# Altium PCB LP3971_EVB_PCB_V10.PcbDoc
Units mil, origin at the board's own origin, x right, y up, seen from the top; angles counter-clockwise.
Board outline 4000 x 4200 mil, 4 copper layers (Top Layer, InternalPlane1, InternalPlane2, Bottom Layer), stack 62 mil thick; 86 components, 62 nets, 253 pads, 86 vias.
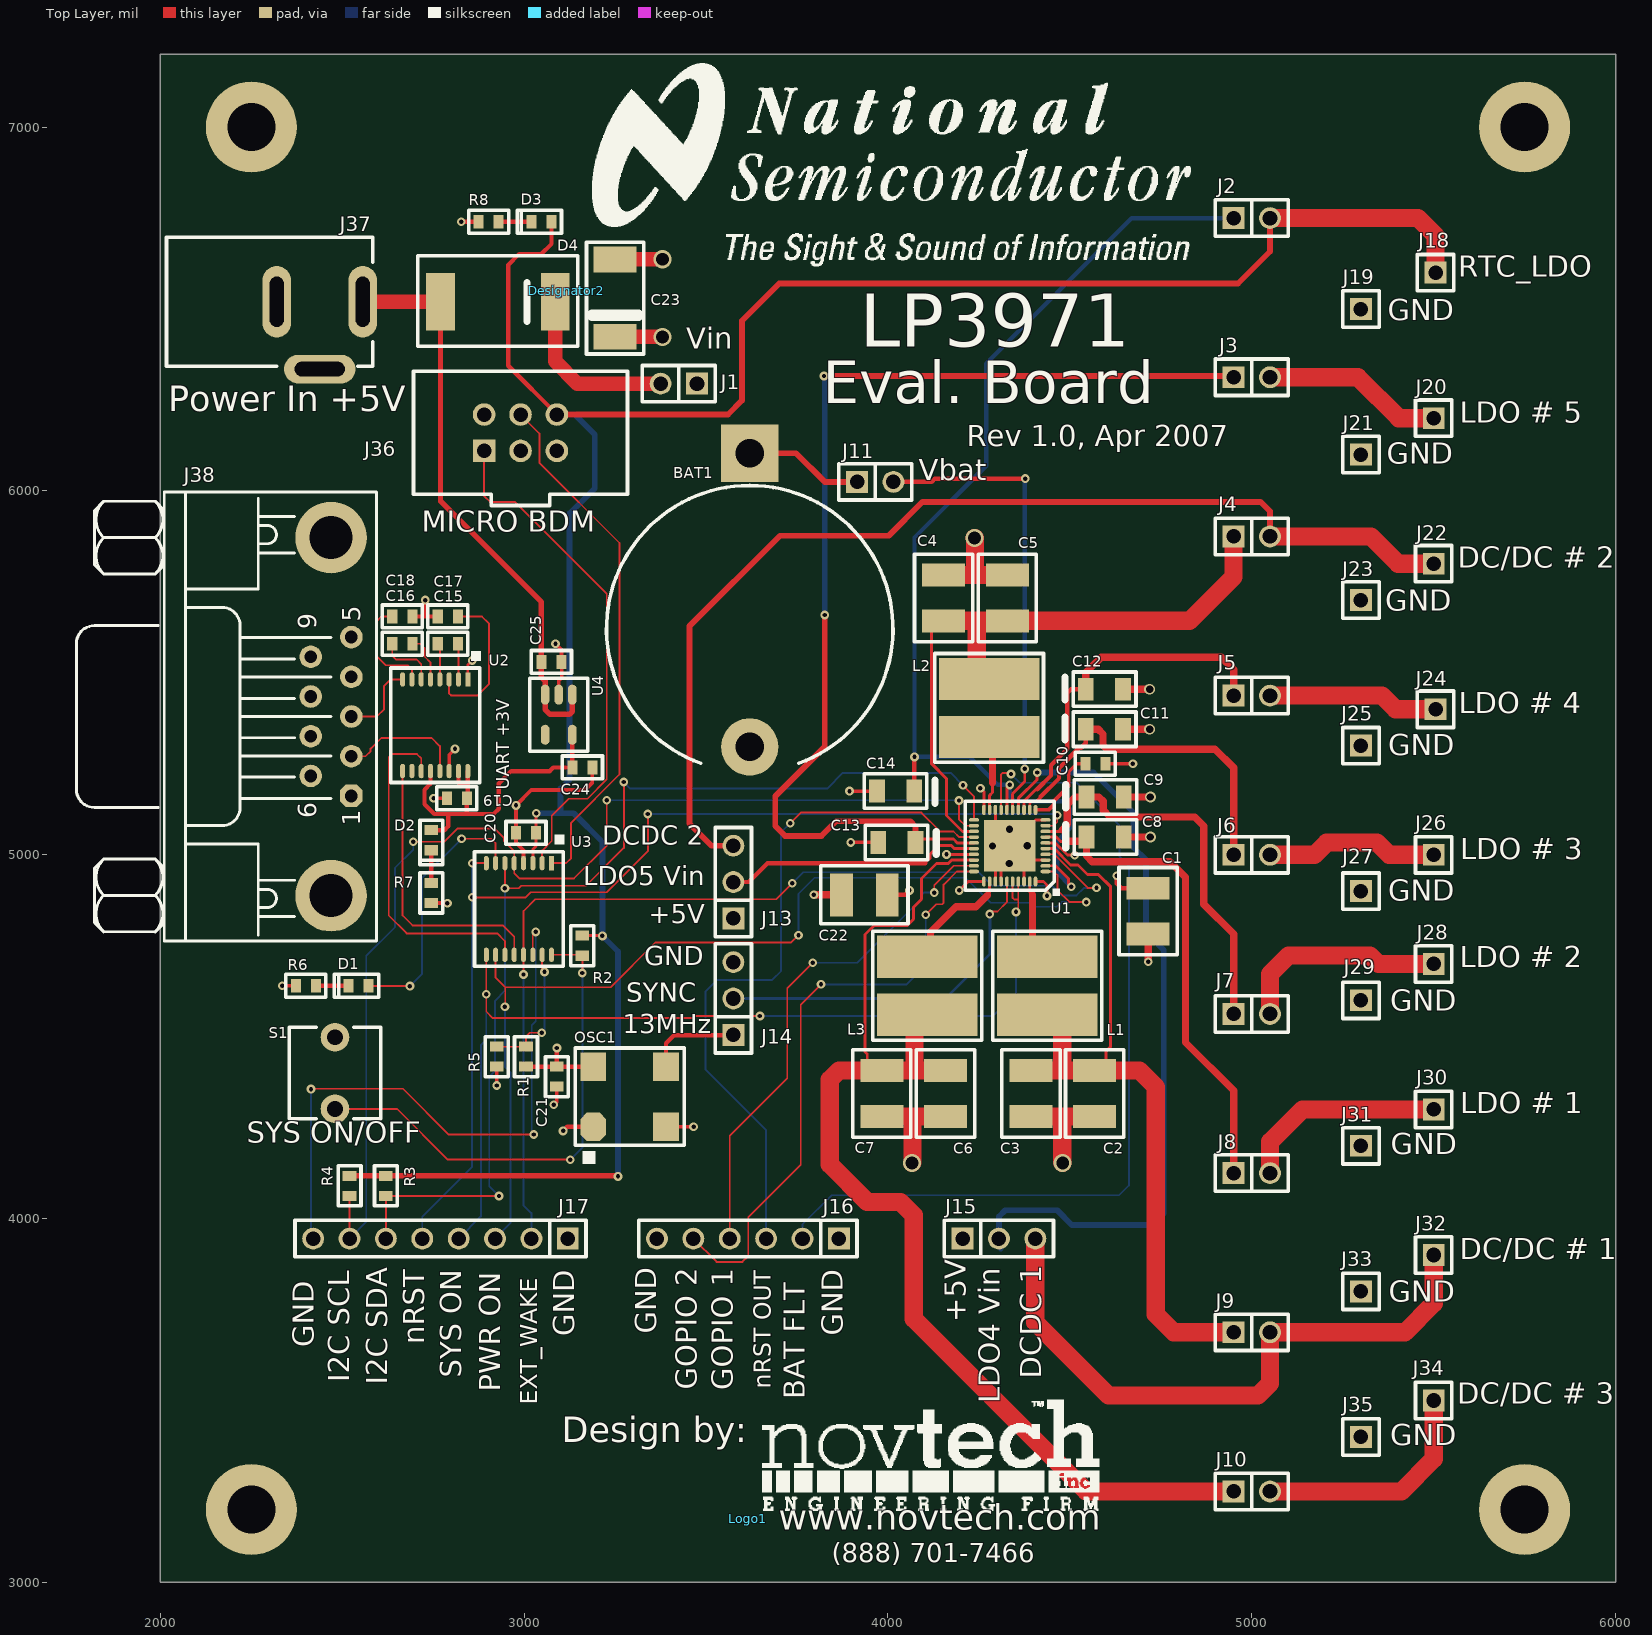
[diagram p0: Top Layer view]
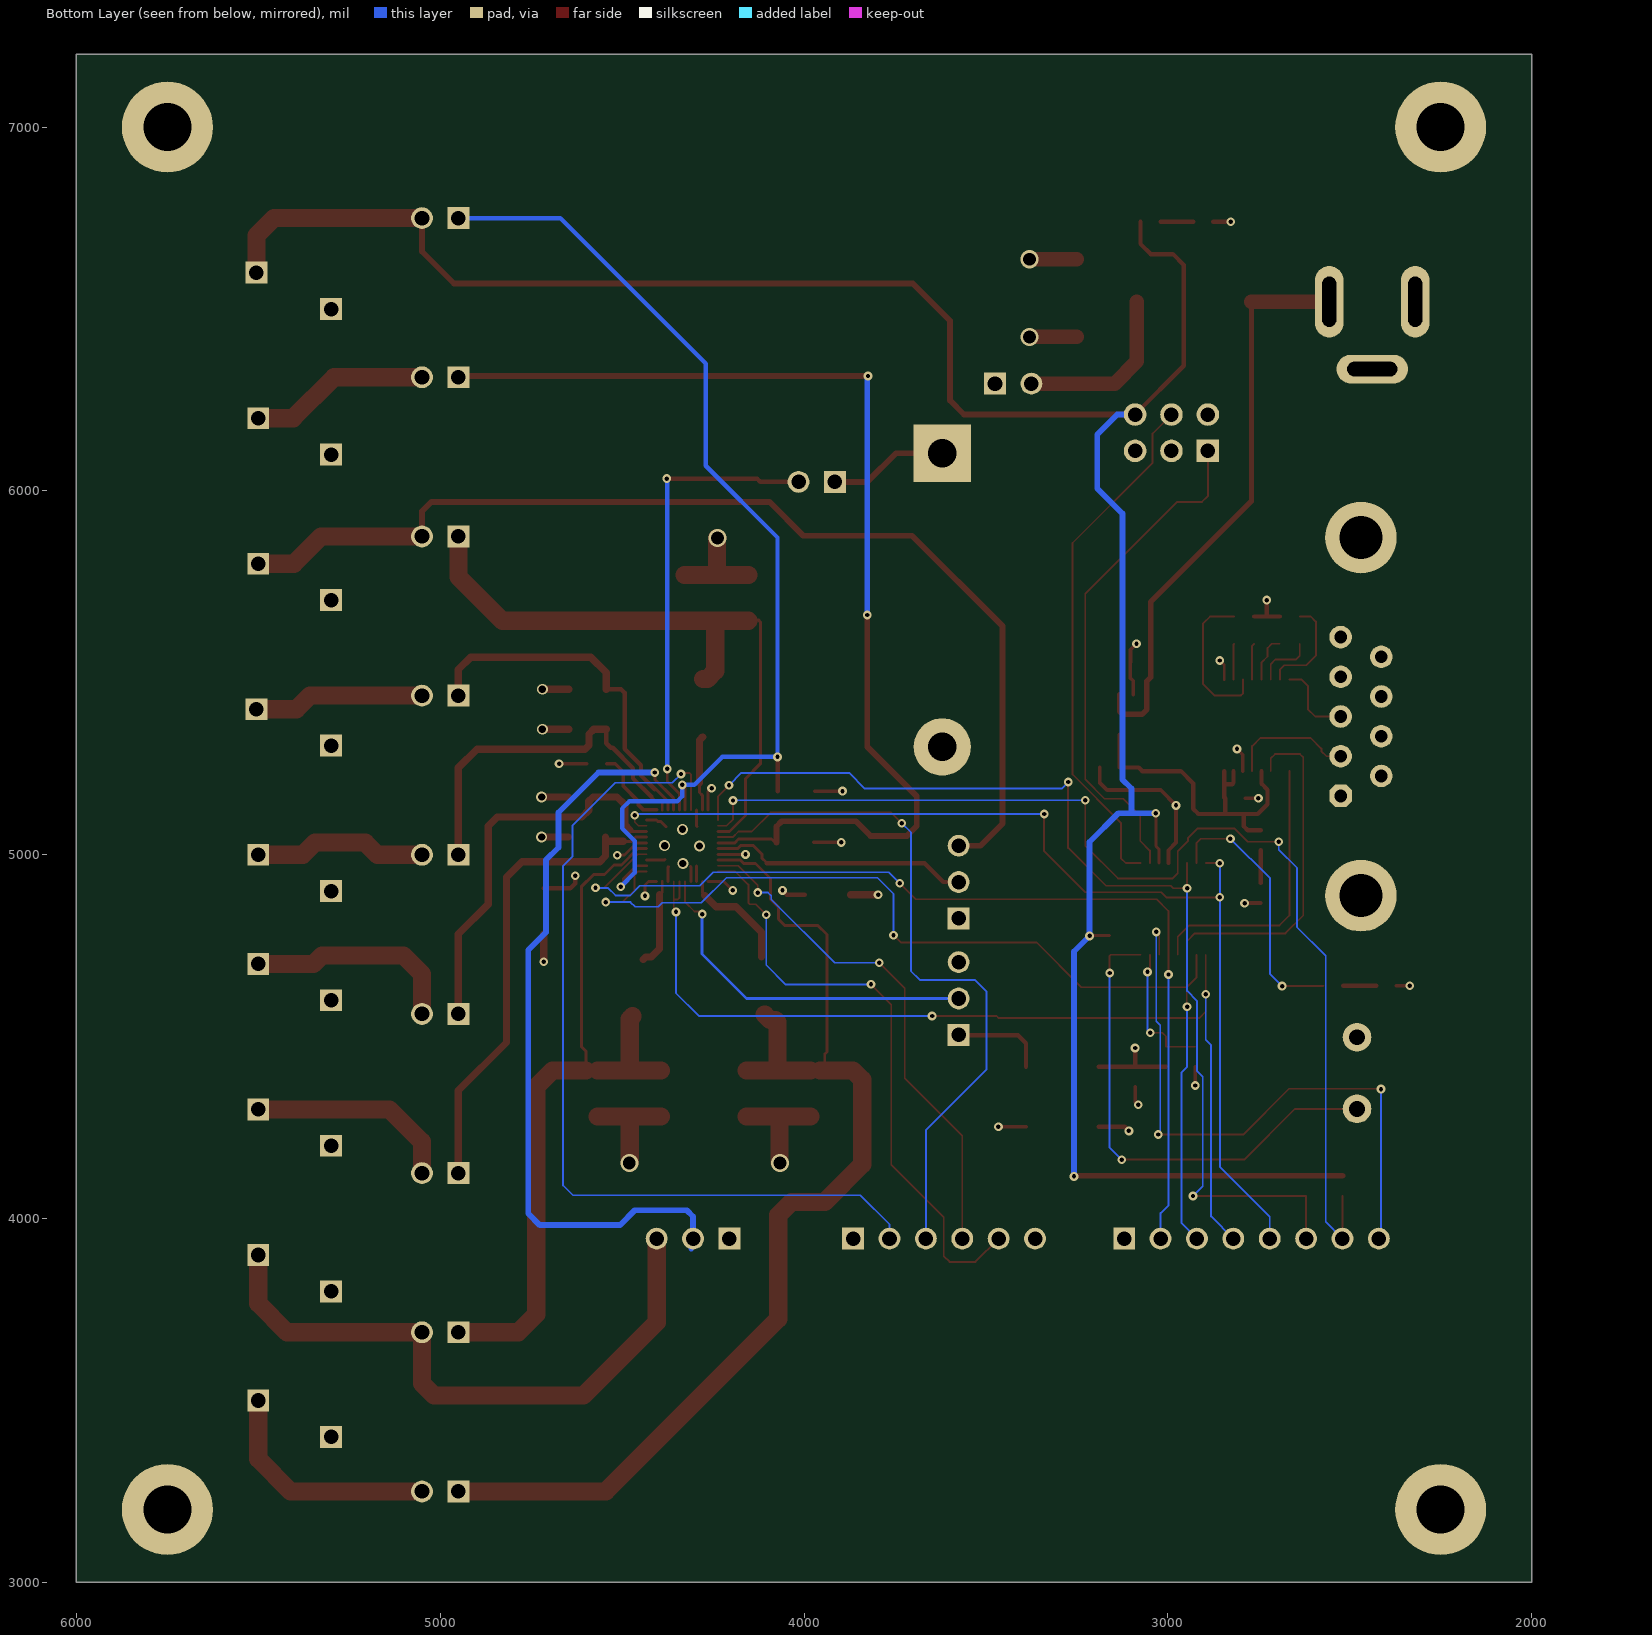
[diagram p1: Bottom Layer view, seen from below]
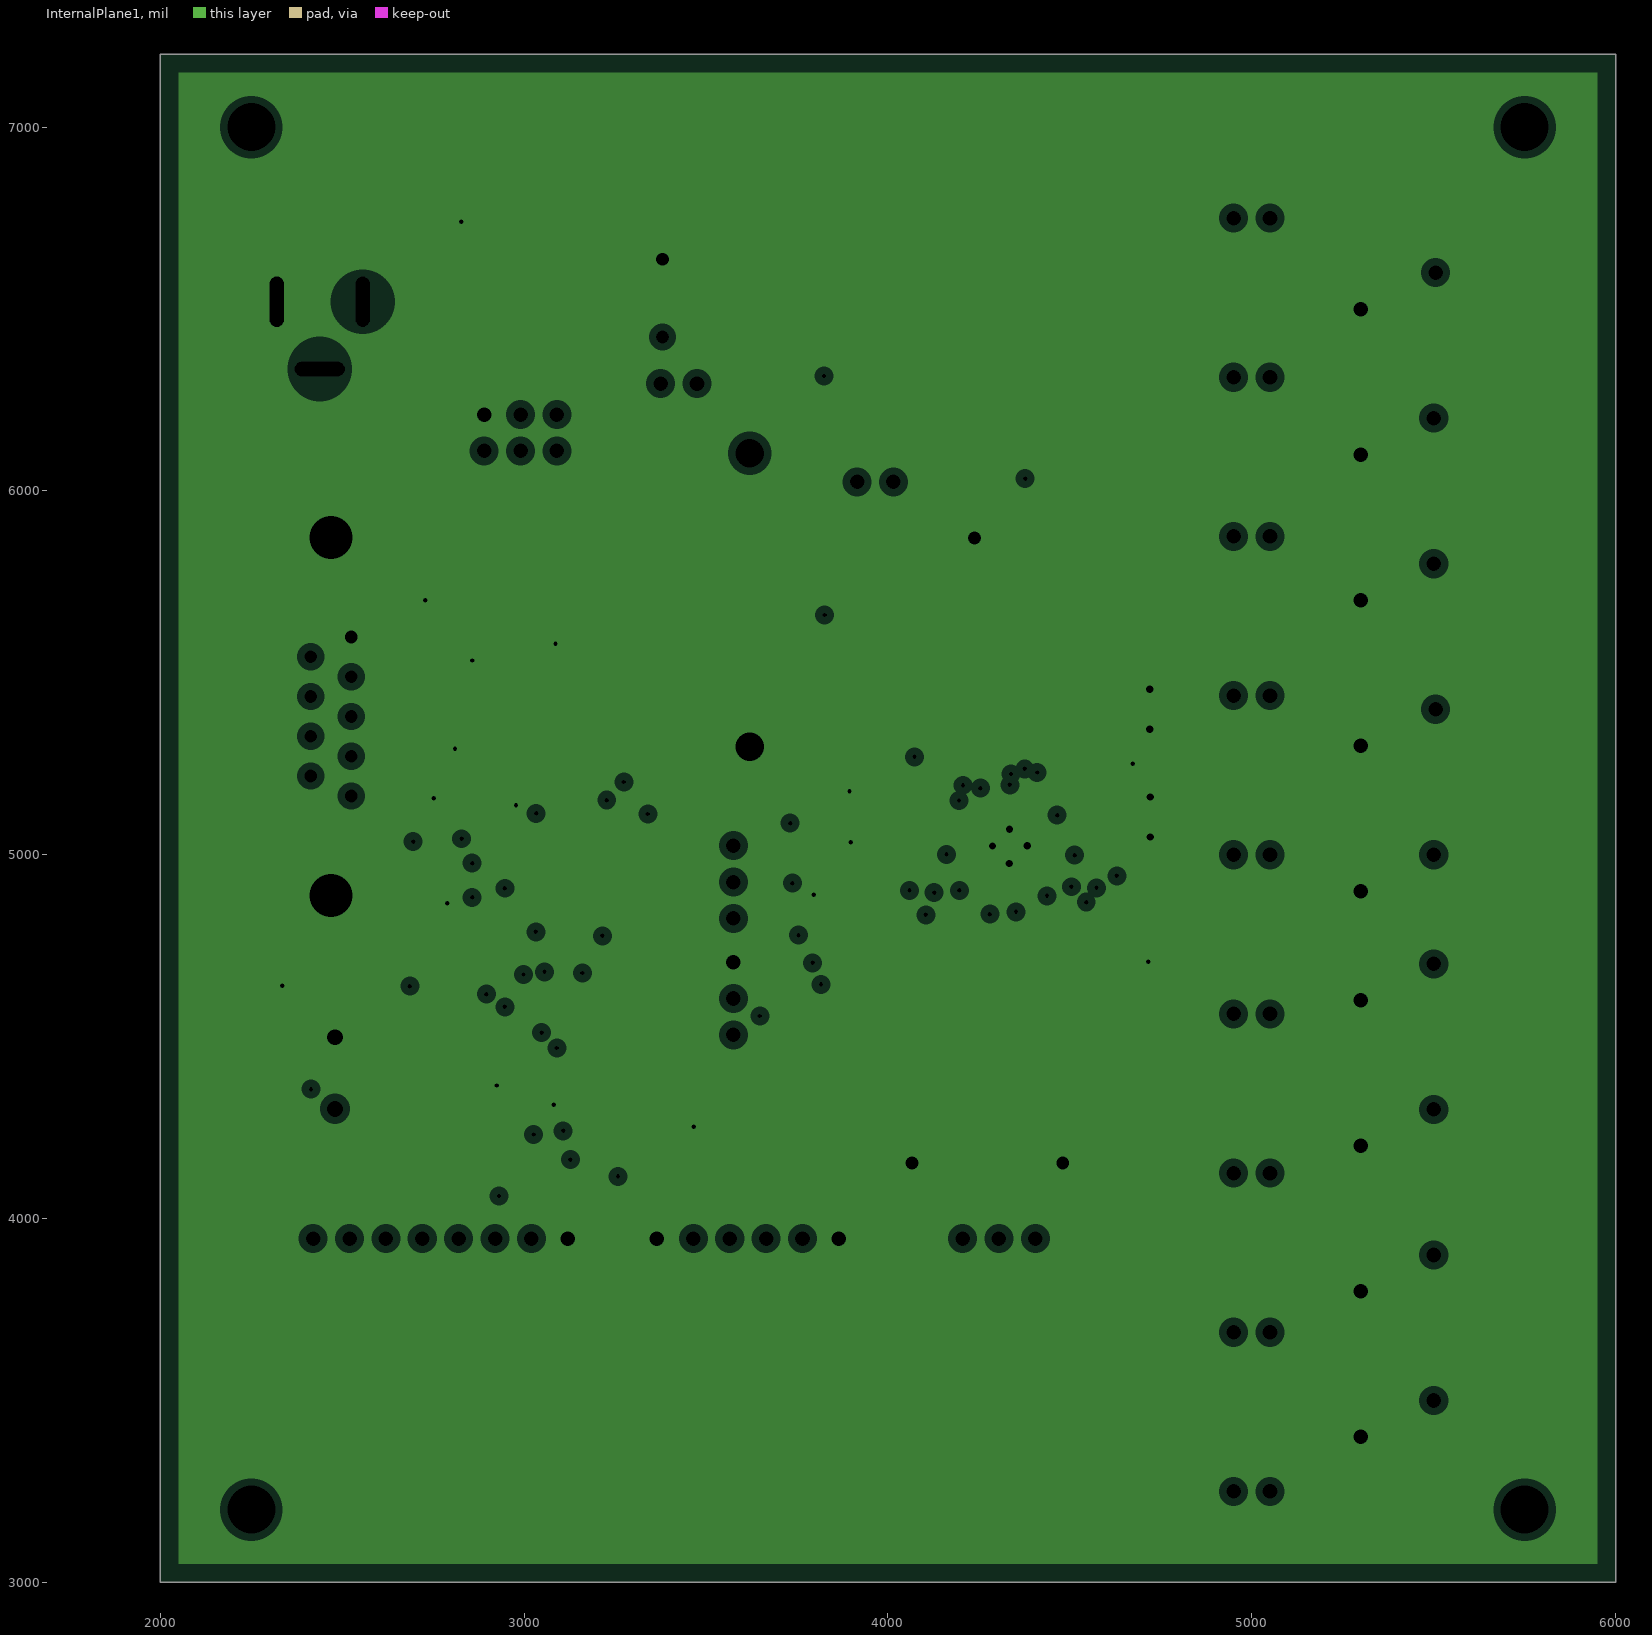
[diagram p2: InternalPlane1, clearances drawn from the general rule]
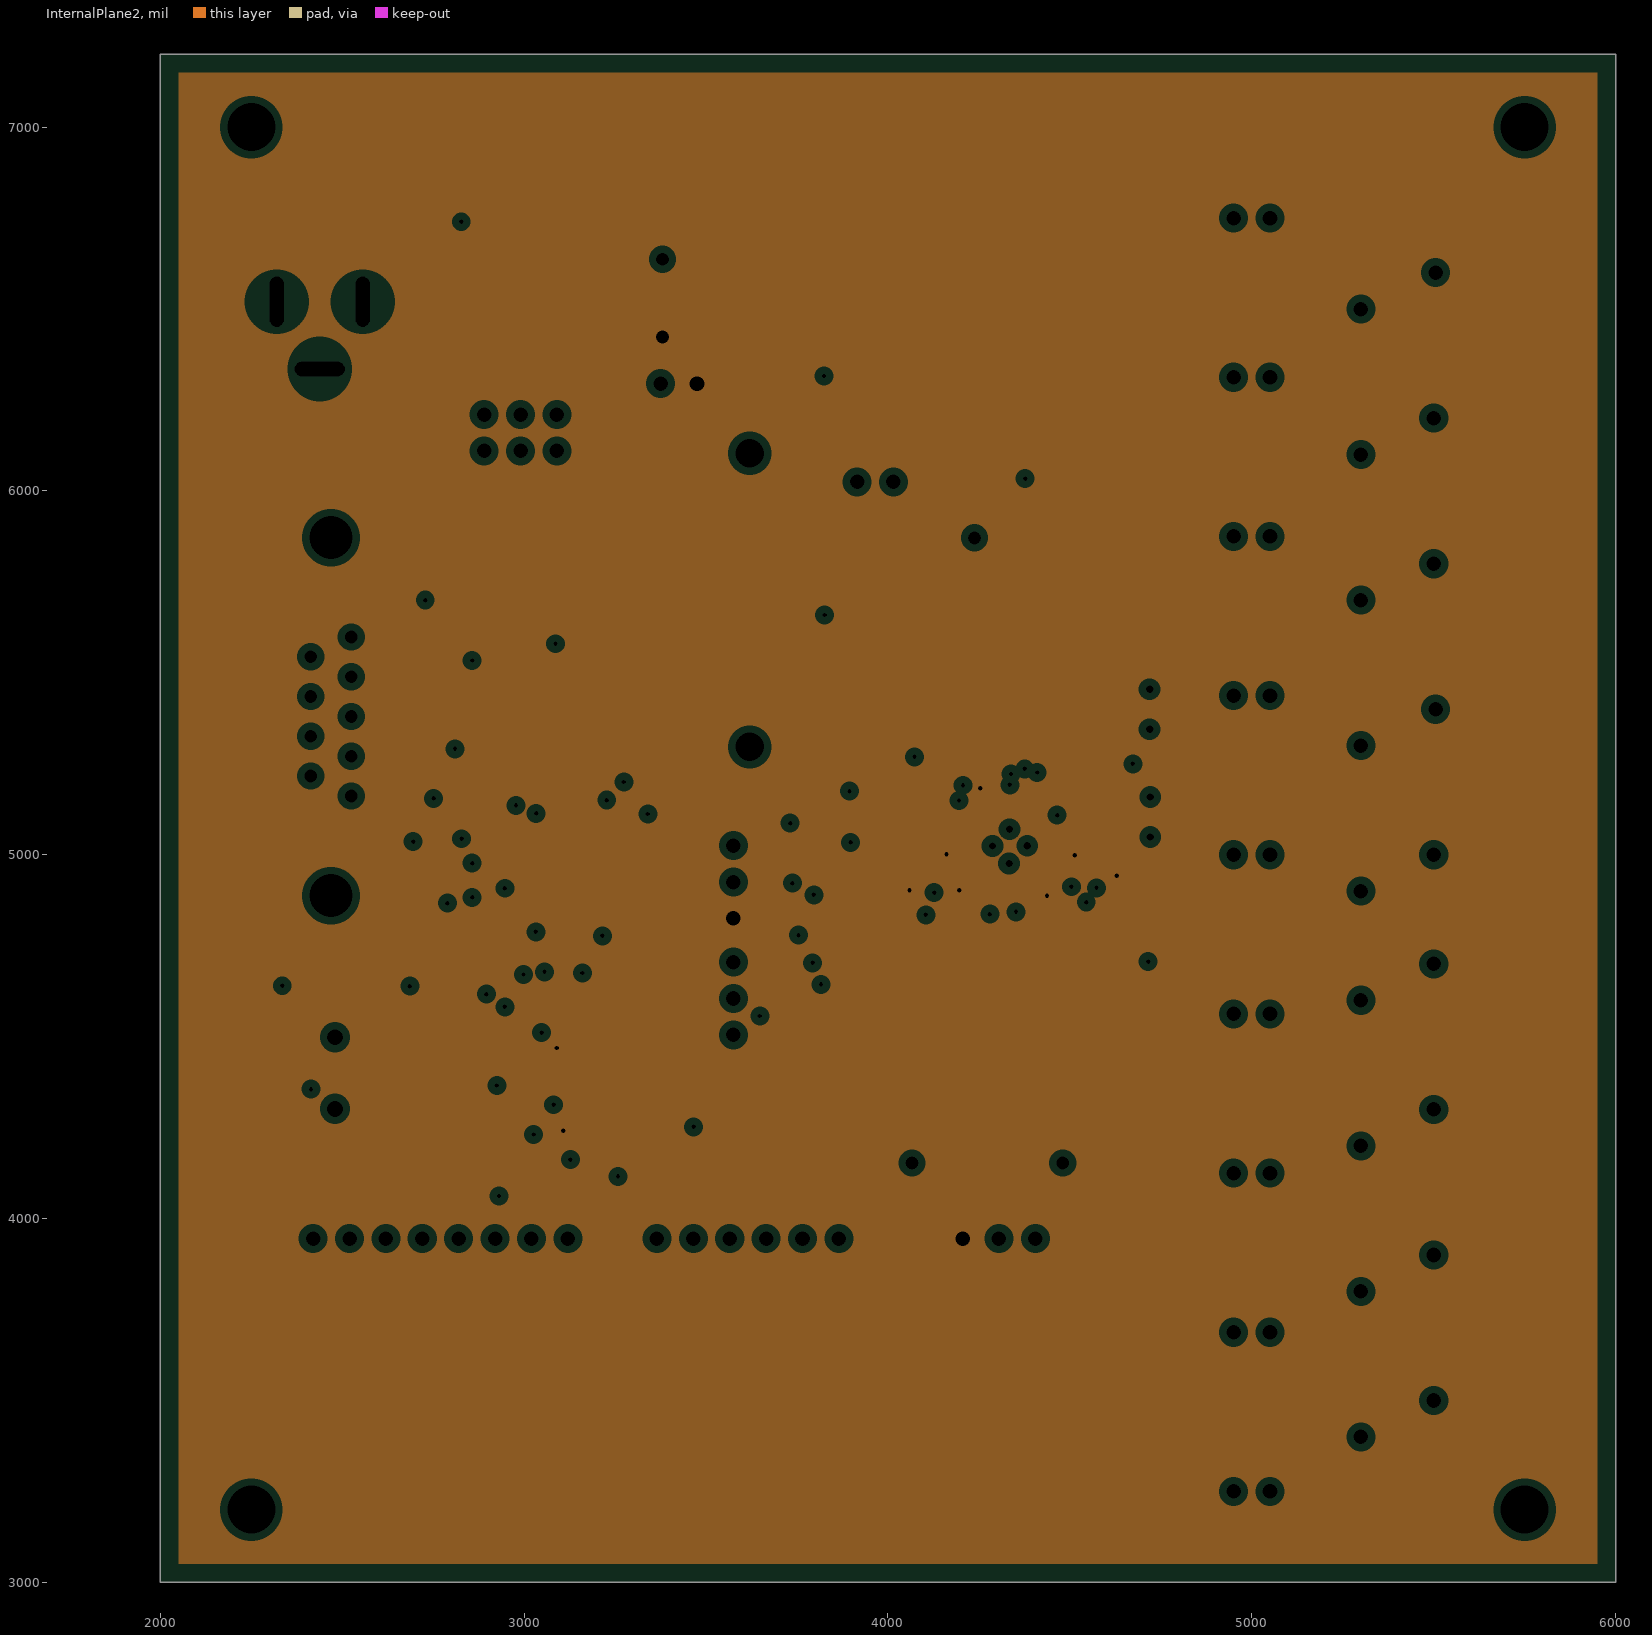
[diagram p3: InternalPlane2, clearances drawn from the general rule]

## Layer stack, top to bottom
Top Layer: signal copper 1.4
Dielectric: prepreg 5, FR-4, Dk 4.8
InternalPlane1: plane copper 1.4, net GND
Dielectric: core 46.4, FR-4, Dk 4.8
InternalPlane2: plane copper 1.4, net +5V
Dielectric: prepreg 5, FR-4, Dk 4.8
Bottom Layer: signal copper 1.4

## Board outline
2000,3000 2000,7200 6000,7200 6000,3000

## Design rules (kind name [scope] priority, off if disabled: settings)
Clearance [All] p1: gap=5
ComponentClearance [All] p1: gap=10 collisioncheckmode=3 verticalgap=10
PlaneClearance [All] p1: clearance=20
PlaneConnect [All] p1: planeconnectstyle=Relief reliefexpansion=20 reliefentries=4 reliefconductorwidth=10 reliefairgap=10
PolygonConnect [All] p1: connectstyle=Relief reliefconductorwidth=10 reliefentries=4 polygonreliefangle="90 Angle"
RoomDefinition LP3971 [InComponentClass('LP3971')] p1: confinementstyle=ConfineIn formatcopy=TRUE lockcomponents=FALSE outline 6045,3017 6507,3017 6507,3337 6045,3337
RoomDefinition "MICRO & Connectors" [InComponentClass('MICRO & Connectors')] p2: confinementstyle=ConfineIn formatcopy=TRUE lockcomponents=FALSE outline 6045,3288 6236,3288 6236,3716 6045,3716
RoutingVias [All] p1: holewidth=12 width=24 viastyle="Through Hole" minholewidth=12 minwidth=24 maxholewidth=70 maxwidth=100
SolderMaskExpansion [All] p1: expansion=4
TestPointUsage [All] p1: valid=0 allowmultiple=FALSE
Testpoint [All] p1: side=15 testpointundercomponent=TRUE minsize=40 maxsize=100 preferedsize=60 minholesize=0 maxholesize=40 preferedholesize=32 testpointgrid=1 style=1023 order=0-112345678
Width [All] p1: maxlimit=100 minlimit=5 preferedwidth=10 minimp=50.000000 maximp=50.000000 favimp=50.000000
16 further rules are at their usual default settings.

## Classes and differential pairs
component class LP3971: BAT1 C1 C2 C3 C4 C5 C6 C7 C8 C9 C10 C11 C12 C13 C14 C22 J2 J3 J4 J5 J6 J7 J8 J9 J10 J11 J13 J15 J16 L1 L2 L3 U1
component class "MICRO & Connectors": C15 C16 C17 C18 C19 C20 C21 C23 C24 C25 D1 D2 D3 D4 J1 J14 J17 J18 J19 J20 J21 J22 J23 J24 J25 J26 J27 J28 J29 J30 J31 J32 J33 J34 J35 J36 J37 J38 OSC1 R1 R2 R3 R4 R5 R6 R7 R8 S1 U2 U3 U4

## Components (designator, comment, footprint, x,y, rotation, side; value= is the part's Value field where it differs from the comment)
BAT1 "BATTERY" "BATTERY ML2020" 3620,5700 r270 top
C1 "10uF/16V" 1210_C 4715,4845 r270 top
C2 "10uF/16V" 1210_C 4568,4344 r270 top
C3 "10uF/16V" 1210_C 4393,4344 r270 top
C4 "10uF/16V" 1210_C 4153,5705.99 r90 top
C5 "10uF/16V" 1210_C 4328,5705.99 r90 top
C6 "10uF/16V" 1210_C 4158,4344 r270 top
C7 "10uF/16V" 1210_C 3983,4344 r270 top
C8 "10uF/10V" "A CASE (3216-18)" 4596.82,5049 r0 top
C9 "10uF/10V" "A CASE (3216-18)" 4596.82,5159 r0 top
C10 "0.01uF/16V" 0603_C 4570,5250 r0 top
C11 "10uF/10V" "A CASE (3216-18)" 4595,5345 r0 top
C12 "10uF/10V" "A CASE (3216-18)" 4595,5455 r0 top
C13 "10uF/10V" "A CASE (3216-18)" 4024.18,5034 r180 top
C14 "10uF/10V" "A CASE (3216-18)" 4021.18,5175 r180 top
C15 "0.1uF" 0603_C 2790,5580 r180 top
C16 "0.1uF" 0603_C 2665,5580 r180 top
C17 "0.1uF" 0603_C 2790,5655 r180 top
C18 "0.1uF" 0603_C 2665,5655 r0 top
C19 "0.1uF" 0603_C 2815,5155 r180 top
C20 "0.1uF" 0603_C 3005,5060 r180 top
C21 "0.1uF" 0603_C 3090,4390 r270 top
C22 "10uF/16V" 1210_C 3935,4890 r180 top
C23 "220uF/6.3V" "C CASE (6032-28)" 3250,6530 r90 top
C24 "1uF" 0603_C 3160,5240 r0 top
C25 "1uF" 0603_C 3075,5530 r180 top
D1 "LED" 0603_LED 2545,4640 r180 top
D2 "LED" 0603_LED 2745,5040 r270 top
D3 "LED" 0603_LED 3047.44,6740 r180 top
D4 "B540C-13-F" SMC 2927.48,6520 r180 top
Designator2 "Comment" ? 3115,6550 r0 top
J1 "JUMPER - SMT" BH2-NP 3475,6295 r180 top
J2 "JUMPER - SMT" BH2-NP 4950,6750 r0 top
J3 "JUMPER - SMT" BH2-NP 4950,6312.5 r0 top
J4 "JUMPER - SMT" BH2-NP 4950,5875 r0 top
J5 "JUMPER - SMT" BH2-NP 4950,5437.5 r0 top
J6 "JUMPER - SMT" BH2-NP 4950,5000 r0 top
J7 "JUMPER - SMT" BH2-NP 4950,4562.5 r0 top
J8 "JUMPER - SMT" BH2-NP 4950,4125 r0 top
J9 "JUMPER - SMT" BH2-NP 4950,3687.5 r0 top
J10 "JUMPER - SMT" BH2-NP 4950,3250 r0 top
J11 "JUMPER - SMT" BH2-NP 3915,6025 r0 top
J13 "JUMPER - 3 WAYS" BH3-NP 3575,4825 r90 top
J14 "JUMPER - 3 WAYS" BH3-NP 3575,4505 r90 top
J15 "JUMPER - 3 WAYS" BH3-NP 4205,3945 r0 top
J16 "CON6" BH6-NP 3865,3945 r180 top
J17 "CON" BH8-NP 3120,3945 r180 top
J18 "CON1" "BH1-NP - 46MIL" 5505,6600 r0 top
J19 "CON1" "BH1-NP - 46MIL" 5300,6500 r0 top
J20 "CON1" "BH1-NP - 46MIL" 5500,6200 r0 top
J21 "CON1" "BH1-NP - 46MIL" 5300,6100 r0 top
J22 "CON1" "BH1-NP - 46MIL" 5500,5800 r0 top
J23 "CON1" "BH1-NP - 46MIL" 5300,5700 r0 top
J24 "CON1" "BH1-NP - 46MIL" 5505,5400 r0 top
J25 "CON1" "BH1-NP - 46MIL" 5300,5300 r0 top
J26 "CON1" "BH1-NP - 46MIL" 5500,5000 r0 top
J27 "CON1" "BH1-NP - 46MIL" 5300,4900 r0 top
J28 "CON1" "BH1-NP - 46MIL" 5500,4700 r0 top
J29 "CON1" "BH1-NP - 46MIL" 5300,4600 r0 top
J30 "CON1" "BH1-NP - 46MIL" 5500,4300 r0 top
J31 "CON1" "BH1-NP - 46MIL" 5300,4200 r0 top
J32 "CON1" "BH1-NP - 46MIL" 5500,3900 r0 top
J33 "CON1" "BH1-NP - 46MIL" 5300,3800 r0 top
J34 "CON1" "BH1-NP - 46MIL" 5500,3500 r0 top
J35 "CON1" "BH1-NP - 46MIL" 5300,3400 r0 top
J36 "3X2" HEADER_BOX_3X2 2890,6110 r0 top
J37 "2.5MM Power Jack" "PJ-002B (POWER JACK)" 2556.22,6520 r180 top
J38 "DB9-F" DB9_F_318 2525,5161.67 r90 top
L1 "2.4uH" ELL6PM 4438,4640 r270 top
L2 "2.4uH" ELL6PM 4278,5403.72 r90 top
L3 "2.4uH" ELL6PM 4108,4640.28 r270 top
Logo1 "Comment" ? 3615,3175 r0 top
OSC1 "12.288MHz" OSC_SMT_7.3X4.8 3290,4335 r0 top
R1 "100K" 0603_R 3005,4445 r270 top
R2 "100K" 0603_R 3160,4750 r90 top
R3 "1.2K" 0603_R 2620,4090 r90 top
R4 "1.2K" 0603_R 2520,4090 r90 top
R5 "100K" 0603_R 2925,4445 r90 top
R6 "100" 0603_R 2400,4640 r180 top
R7 "100" 0603_R 2745,4895 r270 top
R8 "100" 0603_R 2902.44,6740 r180 top
S1 "SW-PB" B3F-602X 2480,4400 r90 top
U1 "LP3971" QFN40P500X500X80-40N 4334.57,5024.87 r180 top
U2 "ICL3221" TSSOP_16 2755.43,5355.98 r180 top
U3 "MC9S08QG4" TSSOP_16 2985.43,4850.98 r180 top
U4 "LP2980" SOT23-5 3095,5385 r0 top

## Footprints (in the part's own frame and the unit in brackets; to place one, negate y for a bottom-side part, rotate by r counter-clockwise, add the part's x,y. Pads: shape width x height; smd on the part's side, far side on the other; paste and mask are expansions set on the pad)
0603_C [mm] "0603 footprint for capasitors"
  rect 0.7x0.95 smd: 1(-0.7,0) 2(0.7,0)
  silkscreen extent -1.4,-0.8 1.4,0.8, body extent -0.9,-0.6 0.9,0.6, height 0.8
0603_LED [mm] "0603 footprint for LED"
  rect 0.7x0.95 smd: A(-0.7,0) K(0.7,0)
  silkscreen extent -1.4,-0.8 1.7,0.8, body extent -0.9,-0.6 0.9,0.6, height 0.45
0603_R [mm] "0603 footprint for resisotrs"
  rect 0.7x0.95 smd: 1(-0.7,0) 2(0.7,0)
  silkscreen extent -1.4,-0.8 1.4,0.8, body extent -0.9,-0.6 0.9,0.6, height 0.45
1210_C [mm] "1210 footprint for capasitors"
  rect 1.6x3 smd: 1(-1.6,0) 2(1.6,0)
  silkscreen extent -3.05,-2.03 3.05,2.03, body extent -2.2,-1.8 2.2,1.8, height 2.5
"A CASE (3216-18)" [mm]
  rect 1.1x1.6 smd: 1(-1.3,0) 2(1.3,0)
  silkscreen extent -2.75,-1.2 2.2,1.2, body extent -1.6,-0.8 1.6,0.8, height 1.8
B3F-602X [mm] "OMRON Momentary Tact Switch"
  round 2 hole 1.1: 1(-2.5,0) 2(2.5,0)
  silkscreen extent -3.2,-3.2 3.2,3.2, body extent -3,-3 3,3, height 5
"BATTERY ML2020" [mm]
  rect 4x4 hole 2: +(-10.25,0)
  round 4 hole 2: -(10.25,0)
  silkscreen extent -8,-10 11.4,10, body extent -5,-7.7 8.6,7.6, height 2.7
"BH1-NP - 46MIL" [mil] "100mil two holes without connecotr installed"
  rect 60x60 hole 40: 1(0,0)
  silkscreen extent -50,-50 50,50, body extent -51,-47 51,49
BH2-NP [mil] "100mil two holes without connecotr installed"
  rect 60x60 hole 40: 1(0,0)
  round 60 hole 40: 2(100,0)
  silkscreen extent -50,-50 150,50, body extent -51,-49 148,49
BH3-NP [mil] "100mil three holes without connecotr installed"
  rect 60x60 hole 40: 1(0,0)
  round 60 hole 40: 2(100,0) 3(200,0)
  silkscreen extent -50,-50 250,50, body extent -47,-47 248,47
BH6-NP [mil] "100mil six holes without connecotr installed"
  rect 60x60 hole 40: 1(0,0)
  round 60 hole 40: 2(100,0) 3(200,0) 4(300,0) 5(400,0) 6(500,0)
  silkscreen extent -50,-50 550,50, body extent -50,-50 550,51
BH8-NP [mil] "100mil seven holes without connecotr installed"
  rect 60x60 hole 40: 1(0,0)
  round 60 hole 40: 2(100,0) 3(200,0) 4(300,0) 5(400,0) 6(500,0) 7(600,0) 8(700,0)
  silkscreen extent -50,-50 750,50, body extent -51,-50 750,51
"C CASE (6032-28)" [mm]
  rect 1.8x3 smd: 1(-2.7,0) 2(2.7,0)
  silkscreen extent -3.9,-2 3.9,2, body extent -3,-1.6 3,1.6, height 2.8
DB9_F_318 [mil]
  oct 62x62 hole 35: 1(0,0)
  round 62 hole 35: 2(109.17,0) 3(218.33,0) 4(327.5,0) 5(436.67,0) 6(55,111.67) 7(164.17,111.67) 8(273.33,111.67) 9(382.5,111.67)
  round 196.67 hole 118.33: G1(-274.17,55.83) G2(710,55.83)
  silkscreen extent -398,-69 835,756, body extent -400,-70 835,735, height 500
ELL6PM [mm] "SMD Power Choke Coil from Panasonic"
  rect 2.95x7 smd: 1(-2.025,0) 2(2.025,0)
  silkscreen extent -3.8,-3.8 3.8,3.8, body extent -3.2,-3.65 3.2,3.65, height 2
HEADER_BOX_3X2 [mil]
  rect 62x62 hole 40: 1(0,0)
  round 62 hole 40: 2(0,100) 3(100,0) 4(100,100) 5(200,0) 6(200,100)
  silkscreen extent -194,-150 394,219, body extent -189,-114 386,214, height 380
OSC_SMT_7.3X4.8 [mm] "Taken from CONNOR WINFILED datasheet"
  oct 1.8x2 smd: 1(-2.54,-2.1)
  rect 1.8x2 smd: 2(2.54,-2.1) 3(2.54,2.1) 4(-2.54,2.1)
  silkscreen extent -3.8,-4.7 3.8,3.4, body extent -3.6,-3.2 3.6,3.2, height 1.15
"PJ-002B (POWER JACK)" [mm] "2.5MM POWER JACK"
  oval 2x5 hole 1 slot 3.5 at 90 deg: 1(0,0) 2(6,0)
  oval 5x2 hole 1 slot 3.5 at 0 deg: 3(3,4.7)
  silkscreen extent -0.7,-4.5 13.7,4.5, body extent -0.51,-4.44 13.72,4.32, height 11
QFN40P500X500X80-40N [mm] "QFN, 40-Leads, Body 5.1x5.1mm (max), Pitch 0.40mm, IPC Medium Density"
  oval 0.7x0.25 smd: 1(-2.5,1.8) 2(-2.5,1.4) 3(-2.5,1) 4(-2.5,0.6) 5(-2.5,0.2) 6(-2.5,-0.2) 7(-2.5,-0.6) 8(-2.5,-1) 9(-2.5,-1.4) 10(-2.5,-1.8) 21(2.5,-1.8) 22(2.5,-1.4) 23(2.5,-1) 24(2.5,-0.6) 25(2.5,-0.2) 26(2.5,0.2) 27(2.5,0.6) 28(2.5,1) 29(2.5,1.4) 30(2.5,1.8)
  oval 0.25x0.7 smd: 11(-1.8,-2.5) 12(-1.4,-2.5) 13(-1,-2.5) 14(-0.6,-2.5) 15(-0.2,-2.5) 16(0.2,-2.5) 17(0.6,-2.5) 18(1,-2.5) 19(1.4,-2.5) 20(1.8,-2.5) 31(1.8,2.5) 32(1.4,2.5) 33(1,2.5) 34(0.6,2.5) 35(0.2,2.5) 36(-0.2,2.5) 37(-0.6,2.5) 38(-1,2.5) 39(-1.4,2.5) 40(-1.8,2.5)
  rect 3.6x3.6 smd paste-2.54: PAD(0,0)
  Assembly Designators Top keep-out region: -3.5,3 -3,3 -3,3.5 -3.5,3.5
  silkscreen extent -3.5,-3.1 3.1,3.5, body extent -2.55,-2.55 2.55,2.55, height 0.8
SMC [mm]
  rect 2x4 smd: A(4,0) C(-4,0)
  silkscreen extent -5.59,-3.2 5.59,3.1, body extent -4,-3.1 4,3.1, height 2.62
SOT23-5 [mm]
  oval 0.6x1.4 smd: 1(0.95,1.4) 2(0,1.4) 3(-0.95,1.4) 4(-0.95,-1.4) 5(0.95,-1.4)
  silkscreen extent -2.03,-2.54 2.03,2.54, body extent -1.7,-1.5 1.7,1.5, height 1.1
TSSOP_16 [mm] "TSSOP 16, 0.65MM pitch (FreeScale 9S08QG8)"
  rect 0.35x1 smd: 1(-2.275,-3.2)
  oval 0.35x1 smd: 2(-1.625,-3.2) 3(-0.975,-3.2) 4(-0.325,-3.2) 5(0.325,-3.2) 6(0.975,-3.2) 7(1.625,-3.2) 8(2.275,-3.2) 9(2.275,3.2) 10(1.625,3.2) 11(0.975,3.2) 12(0.325,3.2) 13(-0.325,3.2) 14(-0.975,3.2) 15(-1.625,3.2) 16(-2.275,3.2)
  silkscreen extent -3.2,-5.2 3.1,4, body extent -2.75,-3.2 2.75,3.2, height 1.2
? [mil]
  silkscreen extent 72,68 1717,626

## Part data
C1 C2 C3 C4 C5 C6 C7 C10 C15 C16 C17 C18 C19 C20 C21 C22 C24 C25: library part CAP_0603, "Capasitor 0603footprint"
C8 C9 C11 C12 C13 C14 C23: library part CAP_TANT
D4: library part DIODE
J13 J14 J15: library part "JUMPER - SMT 3 WAYS", "JUMPER - SMT"
J17: library part CON8
J36: library part HEADER_3X2
J37: library part CON2
L1 L2 L3: library part INDUCTOR
OSC1: library part OSCILLATOR
R1 R2 R3 R4 R5 R6 R7 R8: library part "RESISOTR 0603", "Resistor 0603 footprint"
S1: "Switch"
U1: "Power Management Unit for Advanced Application Processors"
U2: "IC TXRX SGL RS232 3-5.5V"
U3: library part MC9S08QG4CDT, "8 bit MCU from FreeScale"
U4: "Micropowe 50mA LDO"

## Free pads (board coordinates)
  round 250 hole 132 unplated: ""(2250,3200) ""(2250,7000) ""(5750,3200) ""(5750,7000)

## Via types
v1: diameter 24, hole 12, Top Layer to Bottom Layer, 73 vias
v2: diameter 30, hole 20, Top Layer to Bottom Layer, 8 vias
v3: diameter 50, hole 35, Top Layer to Bottom Layer, 5 vias

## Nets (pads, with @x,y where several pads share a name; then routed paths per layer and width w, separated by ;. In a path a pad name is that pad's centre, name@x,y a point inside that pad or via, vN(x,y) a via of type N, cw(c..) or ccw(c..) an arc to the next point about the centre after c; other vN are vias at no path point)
+2.8V_ON: C20.1 D3.A J2.2 J18.1 J36.6 R2.2 R3.2 R4.2 U3.3 | length 6906.2
  Top Layer w8: U3.3 3023.82,5014.82 3032.56,5023.56 C20.1 3032.56,5113.56 v1(3033,5114) ; R2.2 3214.44,4777.56 v1(3215,4777)
  Top Layer w12: D3.A 3075,6679 3047,6651 2986,6651 2956,6621 2956,6344 J36.6
  Top Layer w16: R4.2 R3.2 3256.44,4117.56 v1(3258,4116) ; J36.6 3560,6210 3599,6249 3599,6468 3701,6570 4962,6570 5050,6658 J2.2
  Top Layer w50: J2.2 5457,6750 5505,6702 J18.1
  Bottom Layer w16: v1(3033,5114) 3100,5114 ; J36.6 3139,6210 3194,6155 3194,6007 3125,5938 3125,5207 3100,5182 3100,5114 ; v1(3258,4116) 3258,4734 v1(3215,4777) 3215,5035 3136,5114 3100,5114
+5V: C1.1 C21.1 C22.1 C23.1 J1.1 J13.1 J15.1 OSC1.1 OSC1.4 R1.2 U1.6 U1.20 U1.27 U1.31 U1.40 | length 1009.3
  Top Layer w8: v1(4161,5001) 4161.24,5001.24 U1.27 ; v1(4196,4902) 4220.44,4926.44 U1.31 ; v1(4254,5183) 4263.71,5173.29 U1.20 ; U1.40 4427.56,4926.44 4437,4917 v1(4437,4887) ; U1.6 4459.88,5032.74 4493.62,4999 v1(4513,4999)
  Top Layer w12: R1.2 C21.1@3090,4417.44 ; v1(3090,4469) C21.1 C21.1@3090,4417.44 ; v1(3107,4241) 3118.32,4252.32 OSC1.1 ; OSC1.4 3189.76,4417.44 C21.1@3090,4417.44 ; C22.1 4047,4890 v1(4059,4902) ; v1(4629,4942) 4629,4921 4642.01,4907.99 C1.1
  Top Layer w40: C23.1 3379.3,6423.7 v3(3380,6423)
BATT: BAT1.+ J11.1 | length 327.5
  Top Layer w16: BAT1.+ 3747.46,6103.54 3826,6025 J11.1
BUBATT: J11.2 U1.15 | length 1290.7
  Top Layer w8: U1.15 4342.45,5167.45 4376,5201 v1(4376,5236)
  Top Layer w12: J11.2 4120,6025 4129,6034 v1(4377,6034)
  Bottom Layer w12: v1(4376,5236) 4376,6033 v1(4377,6034)
DCDC_1: J9.2 J15.3 J32.1 | length 1728.4
  Top Layer w50: J15.3 4405,3715 4606,3514 5017,3514 5050,3547 J9.2 5420.5,3687.5 5500,3767 J32.1
DCDC_1_J: C2.1 C3.1 J9.1 L1.2 U1.5 | length 2096.3
  Top Layer w8: U1.5 4457.01,5016.99 4502,4972 4522,4972 4548,4946 4578,4946 4612,4912 4612,4473 4599,4460 4599,4406.99 C2.1
  Top Layer w50: C3.1 C2.1 ; L1.2@4471,4556 4479,4548 4479,4417 ; C2.1@4599,4406.99 4691.01,4406.99 4736,4362 4736,3737 4785.5,3687.5 J9.1
DCDC_2: J4.2 J13.3 J22.1 | length 2986.8
  Top Layer w16: J13.3 3515,5025 3454,5086 3454,5628 3703,5877 4002,5877 4095,5970 5024,5970 5050,5944 J4.2
  Top Layer w50: J4.2 5327,5875 5402,5800 J22.1
DCDC_2_J: C4.1 C5.1 J4.1 L2.2 U1.23 | length 1818
  Top Layer w8: C4.1 4150,5646 4126,5646 4120,5640 4120,5250 4161,5209 4161,5108 4204.76,5064.24 U1.23
  Top Layer w50: C4.1 4244,5643 ; L2.2 4265.55,5483.45 4244,5505 4244,5643 ; J4.1 4950,5764 4829,5643 C5.1 4244,5643
DCDC_3: J10.2 J34.1 | length 647.9
  Top Layer w50: J10.2 5411,3250 5500,3339 J34.1
DCDC_3_J: C6.1 C7.1 J10.1 L3.2 U1.28 | length 3206.5
  Top Layer w8: C7.1 3956.01,4406.99 3942,4421 3943,4422 3943,4452 3937,4458 3937,4781 3962,4806 4053,4806 4070,4823 4070,4856 4092,4878 4092,4935 4133,4976 4165.67,4976 4175.16,4985.5 U1.28
  Top Layer w50: C7.1@3956.01,4406.99 3864.99,4406.99 3840,4382 3840,4149 3943,4046 4034,4046 4071,4009 4071,3724 4545,3250 J10.1 ; C7.1 4073,4406.99 ; L3.2 4093.45,4546 4079,4546 4073,4540 4073,4406.99 ; C6.1 4073,4406.99
GND: BAT1.- C1.2 C2.2 C3.2 C4.2 C5.2 C6.2 C7.2 C8.2 C9.2 C10.2 C11.2 C12.2 C13.2 C14.2 C17.2 C18.2 C19.2 C20.2 C21.2 C22.2 C23.2 C24.2 C25.1 J14.3 J16.1 J16.6 J17.1 J19.1 J21.1 J23.1 J25.1 J27.1 J29.1 J31.1 J33.1 J35.1 J36.2 J37.2 J38.5 J38.G1 J38.G2 OSC1.2 R5.1 R6.2 R7.2 R8.2 S1.2 U1.3 U1.10 U1.18 U1.33 U1.34 U1.38 U1.PAD U2.1 U2.14 U3.4 U4.2 | length 3151.4
  Top Layer w8: U2.1 2845,5522 v1(2857,5534) ; U1.PAD@4294,5078 4295.2,5079.2 U1.18 ; U1.33 4295.2,4968.2 U1.PAD@4296,4969 ; U1.34 4310.95,4966.95 U1.PAD@4312,4968 ; U1.PAD@4373,4967 4373.94,4966.06 U1.38 ; U1.PAD@4379,5077 4393,5091 4401,5091 4405.73,5095.73 U1.10 ; U1.PAD@4382,4987 4383.5,4985.5 U1.3
  Top Layer w10: v1(2335,4640) R6.2 ; R7.2 2788.56,4867.44 v1(2789,4867) ; v1(2751,5155) C19.2 ; U2.14 2793.82,5274.82 v1(2810,5291) ; v1(2925,4366) R5.1 ; U3.4 2998.23,5012.77 2977.44,5033.56 C20.2 v1(2977.44,5135.68) 3019.76,5178 3167,5178 3187.56,5198.56 C24.2 ; v1(3081,4313) 3090,4322 C21.2 ; v1(3086,5580) 3102.56,5563.44 C25.1 3103,5529.56 3103,5486 3095,5478 U4.2 ; OSC1.2 v1(3465.68,4252.32) v1@3466,4252 ; v1(3894.32,5175) C14.2 ; v1(3897.32,5034) C13.2 ; C10.2 v1(4673.24,5250)
  Top Layer w12: C18.2 2728,5655 ; v1(2728,5700) 2728,5655 ; C17.2 2728,5655 ; v1(2827,6740) R8.2
  Top Layer w20: v1(3796.33,4890) C22.2 ; C11.2 v2(4719.18,5345) ; C12.2 v2(4719.18,5455) ; C8.2 v2(4721,5049) ; C9.2 v2(4721,5159) ; v1(4715,4706.33) C1.2
  Top Layer w40: C23.2 3379.3,6636.3 v3(3380,6637)
  Top Layer w50: C7.2 4067,4281.01 ; v3(4066,4153) 4067,4154 4067,4281.01 ; C4.2 4239,5768.98 ; C6.2 4067,4281.01 ; v3(4238,5871) 4239,5870 4239,5768.98 ; C5.2 4239,5768.98 ; C3.2 4479,4281.01 ; v3(4480,4153) 4479,4154 4479,4281.01 ; C2.2 4479,4281.01
  other v2: 4333,4976 4287,5024 4383,5025 4334,5070
LDO_1: J8.2 J30.1 | length 572.9
  Top Layer w50: J8.2 5050,4211 5139,4300 J30.1
LDO_1_J: C8.1 J8.1 U1.7 | length 1334.2
  Top Layer w8: U1.7 4462.51,5048.49 4474,5037 4496,5037
  Top Layer w20: 4496,5037 C8.1@4545.64,5037 ; C8.1 C8.1@4545.64,5037 ; J8.1 4950,4352 4818,4484 4818,4938 4775,4981 4561,4981 4545.64,4996.36 C8.1@4545.64,5037
LDO_2: J7.2 J28.1 | length 590.2
  Top Layer w50: J7.2 5050,4672 5101,4723 5325,4723 5348,4700 J28.1
LDO_2_J: C9.1 J7.1 U1.8 | length 1104.7
  Top Layer w8: U1.8 4474.24,5064.24 4478,5068
  Top Layer w20: 4478,5068 4493,5083 4493,5138 4514,5159 C9.1 4580,5159 4592,5147 4592,5122 4610,5104 4843,5104 4868,5079 4868,4864 4950,4782 J7.1
LDO_3: J6.2 J26.1 | length 478.2
  Top Layer w50: J6.2 5172,5000 5206,5034 5344,5034 5378,5000 J26.1
LDO_3_J: C11.1 J6.1 U1.12 | length 1004.5
  Top Layer w8: U1.12 4389.69,5142.69 4394,5147 4409,5147 4420,5158 4420,5160
  Top Layer w12: 4420,5160 4470,5210 4470,5238 4526,5294 4531,5294 4543.82,5306.82 C11.1
  Top Layer w20: C11.1 4578,5345 4591,5332 4591,5301 4602,5290 4899,5290 4950,5239 J6.1
LDO_4: J5.2 J24.1 | length 470.5
  Top Layer w50: J5.2 5357.5,5437.5 5395,5400 J24.1
LDO_4_J: C12.1 J5.1 U1.13 | length 982.8
  Top Layer w8: U1.13 4373.94,5146.94 4407,5180 4410,5180
  Top Layer w12: 4410,5180 4448,5218 4448,5246 4493,5291 4493,5445 4503,5455 C12.1
  Top Layer w20: C12.1 4543.82,5500.82 4586,5543 4916,5543 4950,5509 J5.1
LDO_5: J3.2 J20.1 | length 496.6
  Top Layer w50: J3.2 5291.5,6312.5 5404,6200 J20.1
LDO_5_J: C13.1 J3.1 U1.25 | length 3053.1
  Top Layer w8: C13.1 4080,5034 4089,5043 4180,5043 4190.26,5032.74 U1.25
  Top Layer w16: v1(3824,6316) 4946.5,6316 J3.1 ; v1(3826,5659) 3826,5297 3690,5161 3690,5079 3717,5052 3817,5052 3857,5092 4061,5092 4075.36,5077.64 C13.1
  Bottom Layer w16: v1(3824,6316) 3826,6314 v1(3826,5659)
MCU_+3.0V: C19.1 C24.1 D2.A U2.12 U2.15 U2.16 U4.5 | length 962.5
  Top Layer w12: U2.12 2742.64,5195.64 2726,5179 2726,5139 2753,5112 2791,5112 ; D2.A 2780.56,5067.56 2791,5078 2791,5112 ; U2.15 2819.41,5197.59 2823,5194 2845,5194 ; U2.16 2845,5194 ; U4.5 3132.44,5329.84 C24.1 3080,5240 3070,5230 2964,5230 2930,5196 2930,5126 2916,5112 2842,5112 ; 2791,5112 2842,5112 ; 2842,5112 2842,5154.44 C19.1 2845,5157.44 2845,5194
MCU_PTA2: J17.8 U3.14 | length 1699.6
  Top Layer w5: v1(2414,4356) 2415,4357 2667,4357 2793,4231 v1(3026,4231) ; U3.14 3023.82,4779.82 v1(3032,4788)
  Bottom Layer w5: J17.8@2414,3951 v1(2414,4356) ; v1(3026,4231) 3021,4236 3021,4531 3032,4542 v1(3032,4788)
MICRO_2V8_BDM_BKGD: J36.1 U3.2 | length 1415.9
  Top Layer w5: J36.1 2890,5986 2906,5970 2974,5970 3227,5717 3227,5207 3174,5154 3123,5154 3075.77,5106.77 3075.77,5037.77 3049.41,5011.41 U3.2
MICRO_2V8_BDM_RESET: J36.4 U3.1 | length 1446.6
  Top Layer w5: J36.4 3042,6158 3042,6077 3262,5857 3262,5221 3129,5088 3129,4991 3114.97,4976.97 U3.1
MICRO_2V8_SCL: J17.7 R4.1 U1.22 U3.5 | length 3155.3
  Top Layer w5: J17.7 R4.1 ; v1(2695,5036) 2780,5036 2816,5072 2919,5072 2945,5046 2945,5037 2972.64,5009.36 U3.5 2972.64,4949.36 2987,4935 3137,4935 3227,5025 v1(3227,5150) ; v1(4195,5149) 4195,5098 4213.02,5079.98 U1.22
  Bottom Layer w5: J17.7 2566,3991 2566,4722 2645,4801 2645,4964 2695,5014 v1(2695,5036) ; v1(3227,5150) 4194,5150 v1(4195,5149)
MICRO_2V8_SDA: J17.6 R3.1 U1.21 U3.6 | length 3005.6
  Top Layer w5: J17.6 R3.1 2620.44,4062 v1(2931,4062) ; v1(2947,4908) v1(2947,4908) ; U3.6 v1(2947,4908) ; v1(3274,5200) 3274,5019 3170,4915 2992,4915 2985.05,4908.05 v1(2947,4908) ; v1(4206,5191) 4236.15,5160.85 U1.21
  Bottom Layer w5: v1(2931,4062) 2904,4089 2904,4390 2920,4406 2920,4599 2947,4626 v1(2947,4908) ; v1(3274,5200) 3292,5182 3833,5182 3876,5225 4172,5225 v1(4206,5191)
MICRO_PM_2V8_NRST: J17.5 U1.9 U3.8 | length 2946.6
  Top Layer w5: v1(2857,4883) 3004,4883 3018,4897 3227,4897 3340,5010 v1(3340,5112) ; v1(2857,4977) U3.8 ; U1.9 4454.98,5079.98 4465,5090 v1(4465,5109)
  Bottom Layer w5: J17.5 2720,4005 2857,4142 v1(2857,4883) v1(2857,4977) ; v1(3340,5112) 4462,5112 v1(4465,5109)
MICRO_PM_2V8_POWER_ON: J17.3 U1.1 U3.10 | length 2813.4
  Top Layer w5: U3.10 2921.46,4662.54 2948,4636 ; v1(2947,4582) 2948,4582 2948,4636 ; v1(3754,4779) 3734,4759 3361,4759 3238,4636 2948,4636 ; U1.1 4456,4954 4466,4944 4466,4903 4499,4870 v1(4545,4870)
  Bottom Layer w5: J17.3 2962,3987 2962,4402 2947,4417 v1(2947,4582) ; v1(3754,4779) 3754,4893 3798,4937 4213,4937 4282,4868 4390,4868 4401,4857 4464,4857 4477,4870 v1(4545,4870)
MICRO_RXD: U2.9 U3.12 | length 777.3
  Top Layer w5: U2.9 2665.87,4833.13 2693,4806 2941,4806 2972.64,4774.36 U3.12
MICRO_TXD: U2.11 U3.11 | length 953.8
  Top Layer w5: U2.11 2717.05,5264.95 2705,5277 2637,5277 2628,5268 2628,4833 2677,4784 2926.05,4784 2947.05,4763 U3.11
MICTO_PM_2V8_EXT_WAKEUP: J17.2 U1.4 U3.13 | length 2741.9
  Top Layer w5: v1(2998,4671) 2998.23,4671.23 U3.13 2998.23,4845.23 3031,4878 3693,4878 v1(3737,4922) ; U1.4 4456.49,5001.24 4548.74,4909 v1(4573,4909)
  Bottom Layer w5: v1(2998,4671) 2998,4037 3020,4015 J17.2 ; v1(3737,4922) 3767,4952 4250,4952 4287,4915 4451,4915 4478,4888 4518,4888 4539,4909 v1(4573,4909)
MICTO_PM_2V8_SYS_ON: J17.4 U1.36 U1.37 U3.9 | length 2723.3
  Top Layer w5: U3.9 v1@2895.87,4617.13 ; v1(2896,4617) v1@2895.87,4617.13 ; v1(3648,4557) 3471,4557 3465,4551 2914,4551 2895.87,4569.13 2895.87,4617 v1@2895.87,4617.13 ; U1.36 4342.45,4881.55 4347,4877 4358.2,4877 ; v1(4352,4843) 4358.2,4849.2 4358.2,4877 ; U1.37 4358.2,4877
  Bottom Layer w5: J17.4 2881,4006 2881,4477 2896,4492 v1(2896,4617) ; v1(3648,4557) 4289,4557 4352,4620 v1(4352,4843)
MP_NRSTO: J16.3 U1.24 | length 1941.3
  Top Layer w5: v1(3731,5087) 3760,5116 4092,5116 4144,5064 4180,5064 4195.51,5048.49 U1.24
  Bottom Layer w5: J16.3 3665,4243 3498,4410 3498,4623 3531,4656 3682,4656 3706,4680 3706,5062 v1(3731,5087)
NetD1_K: D1.K R6.1 | length 89.9
  Top Layer w12: R6.1 D1.K
NetD2_K: D2.K R7.1 | length 89.9
  Top Layer w12: R7.1 D2.K
NetD3_K: D3.K R8.1 | length 89.9
  Top Layer w12: R8.1 D3.K
NetD4_C: D4.C J1.2 | length 479.3
  Top Layer w40: D4.C 3084.96,6356.04 3146,6295 J1.2
NetJ14_1: J14.1 OSC1.3 | length 258.8
  Top Layer w12: OSC1.3 3390,4482 3412,4504 3574,4504 J14.1
PM_BATT_FLT: J16.2 U1.17 | length 2465.1
  Top Layer w5: U1.17 4310.95,5220.95 4315,5225 4335,5225 v1(4338,5222)
  Bottom Layer w5: J16.2 3765,3984 3845,4064 4635,4064 4662,4091 4662,4970 4636,4996 4636,5081 4519,5198 4362,5198 v1(4338,5222)
PM_GPIO1: J16.4 U1.29 | length 1423.7
  Top Layer w5: J16.4 3565,4228 3723,4386 3723,4633 v1(3793,4703) ; v1(4127,4896) 4127,4916 4180.75,4969.75 U1.29
  Bottom Layer w5: v1(3793,4703) 3916,4703 4090,4877 4090,4887 4099,4896 v1(4127,4896)
PM_GPIO2: J16.5 U1.30 | length 1673.5
  Top Layer w5: J16.5 3529,3881 3600,3881 3616,3897 3616,4004 3760,4148 3760,4588 v1(3816,4644) ; v1(4104,4835) 4133,4864 4149,4864 4153,4868 4153,4918 4189,4954 U1.30
  Bottom Layer w5: v1(3816,4644) 3817,4643 4050,4643 4104,4697 v1(4104,4835)
PM_RTC_LDO: C14.1 J2.1 U1.2 U1.16 | length 3028
  Top Layer w8: U1.16 4326.7,5183.7 v1(4335,5192) ; U1.2 4460.25,4969.75 4496,4934 4496,4920 v1(4504,4912)
  Top Layer w12: C14.1 4072.36,5268.36 v1(4073,5269)
  Bottom Layer w12: v1(4504,4912) 4465,4951 4465,5038 4500,5073 4500,5127 4480,5147 4348,5147 4335,5160 v1(4335,5192) 4302,5192 4225,5269 v1(4073,5269) 4073,5872 4270,6069 4270,6350 4670,6750 J2.1
PM_SW1: L1.1 U1.39 | length 244.9
  Top Layer w8: U1.39 4389.69,4897.31 4397,4890
  Top Layer w20: 4397,4890 4397,4742 4420,4719 4435,4719 4436.14,4717.86 L1.1@4442,4712
PM_SW2: L2.1 U1.19 | length 207.6
  Top Layer w8: U1.19 4279.46,5163.46 4287,5171 4287,5198
  Top Layer w20: L2.1 4287,5315 4287,5198
PM_SW3: L3.1 U1.32 | length 307
  Top Layer w8: 4273,4888 4279.46,4894.46 U1.32
  Top Layer w20: L3.1@4117,4719 4117,4720 4117,4787 4187,4857 4242,4857 4273,4888
PM_UP: D1.A U3.7 | length 730.9
  Top Layer w5: D1.A 2573.56,4639 v1(2686,4639) ; v1(2828,5044) 2909,5044 2921.46,5031.54 U3.7
  Bottom Layer w5: v1(2686,4639) 2719,4672 2719,4935 v1(2828,5044)
PM_VIN_LDO4: J15.2 U1.14 | length 2149.4
  Top Layer w8: U1.14 4358.2,5155.2 4410,5207 v1(4410,5226)
  Bottom Layer w16: J15.2 4305,4006 4322,4023 4465,4023 4506,3982 4726,3982 4758,4014 4758,4738 4709,4787 4709,4986 4675,5020 4675,5116 4565,5226 v1(4410,5226) ; J15.2@4310,3918 J15.2@4310,3945
PM_VIN_LDO5: J13.2 U1.26 | length 713.2
  Top Layer w8: 4102,4977 4116,4991 4116,5002 4140,5026 4173,5026 4182.01,5016.99 U1.26
  Top Layer w12: J13.2 3617,4925 3669,4977 4102,4977
PM_VREF: C10.1 U1.11 | length 218.2
  Top Layer w10: U1.11 4441.29,5123.29 4456,5138 4456,5148 4497,5189 4497,5228 4519,5250 C10.1
POWER_IN_DETECT: R1.1 R5.2 U3.15 | length 375.6
  Top Layer w5: R5.2 R1.1 3005,4501 3015,4511 v1(3048,4511) ; U3.15 3049.41,4684.59 v1(3056,4678)
  Bottom Layer w5: v1(3048,4511) 3056,4519 v1(3056,4678)
RX_RS232: J38.3 U2.8 | length 220.6
  Top Layer w5: J38.3 2595,5380 2615,5400 2615,5464 2632.97,5481.97 U2.8
SYNC_CLK_5V: J14.2 U1.35 | length 982.5
  Top Layer w5: v1(4280,4837) 4287,4844 4301,4844 4326.7,4869.7 U1.35
  Bottom Layer w8: J14.2 4158,4605 4280,4727 v1(4280,4837)
SYS_ON_OFF: R2.1 S1.1 U3.16 | length 1365
  Top Layer w5: S1.1 2650.43,4301.57 2790,4162 v1(3127,4162) ; U3.16 3157.44,4725 R2.1 v1(3160,4675)
  Bottom Layer w5: v1(3127,4162) 3160,4195 v1(3160,4675)
TX_RS233: J38.2 U2.13 | length 346.1
  Top Layer w5: J38.2 2563.83,5270.83 2578,5285 2578,5292 2607,5321 2746,5321 2768.23,5298.77 U2.13
UART__C2+: C16.1 U2.5 | length 131.3
  Top Layer w5: C16.1 2714,5580 2726,5568 2726,5545 2742.64,5528.36 U2.5
UART_C1+: C15.1 U2.2 | length 98.8
  Top Layer w5: C15.1 2819.41,5578.15 U2.2
UART_C1-: C15.2 U2.4 | length 100.4
  Top Layer w5: C15.2 2768.23,5574.21 U2.4
UART_C2-: C16.2 U2.6 | length 164.4
  Top Layer w5: C16.2 2637.44,5546.56 2647,5537 2704,5537 2717.05,5523.95 U2.6
UART_V+: C17.1 U2.3 | length 423.3
  Top Layer w5: U2.3 2793.82,5443.18 2799,5438 2872,5438 2903,5469 2903,5636 2884,5655 C17.1
UART_V-: C18.1 U2.7 | length 285.8
  Top Layer w5: C18.1 2607,5655 2593,5641 2593,5547 2619,5521 2680,5521 2691.46,5509.54 U2.7
VIN: C25.2 D4.A J37.1 U4.1 U4.3 | length 1583.1
  Top Layer w15: D4.A 2770,5972 3047.44,5694.56 C25.2 3047.44,5487.56 3057.6,5477.4 U4.3 3057.6,5399.4 3071,5386 3124,5386 3132.4,5394.4 U4.1
  Top Layer w40: J37.1 D4.A
pads on no net: J36.3 J36.5 J37.3 J38.1 J38.4 J38.6 J38.7 J38.8 J38.9 U2.10 U4.4

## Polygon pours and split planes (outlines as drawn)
GND on InternalPlane1 (split plane): 5949.57,3050.43 2050.43,3050.43 2050.43,7149.57 5949.57,7149.57
+5V on InternalPlane2 (split plane): 5949.57,3050.43 2050.43,3050.43 2050.43,7149.57 5949.57,7149.57

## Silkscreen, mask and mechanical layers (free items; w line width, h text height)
Top Overlay:
  text "RTC_LDO" at 5568,6570 h100
  text "GND" at 5373,6450 h100
  text "Vin" at 3446,6372 h100
  text "LP3971" at 3923,6348 h250
  text "Eval. Board" at 3820,6203 h200
  text "Power In +5V" at 2022,6196 h120
  text "LDO # 5" at 5572,6168 h100
  text "Rev 1.0, Apr 2007" at 4216,6103 h100
  text "GND" at 5371,6055 h100
  text "Vbat" at 4084,6010 h100
  text "MICRO BDM" at 2718,5869 h100
  text "DC/DC # 2" at 5566,5769 h100
  text "GND" at 5367,5652 h100
  text "LDO # 4" at 5569,5370 h100
  text "GND" at 5375,5254 h100
  text "UART +3V" at 2972,5179 h60 r90
  text "DCDC 2" at 3215,5010 h90
  text "LDO # 3" at 5573,4969 h100
  text "LDO5 Vin" at 3163,4899 h90
  text "GND" at 5375,4855 h100
  text "+5V" at 3343,4794 h90
  text "GND" at 3330,4678 h90
  text "LDO # 2" at 5571,4672 h100
  text "SYNC" at 3281,4578 h90
  text "GND" at 5380,4552 h100
  text "13MHz" at 3271,4492 h90
  text "LDO # 1" at 5573,4270 h100
  text "SYS ON/OFF" at 2238,4189 h100
  text "GND" at 5382,4157 h100
  text "DC/DC # 1" at 5571,3869 h100
  text "GND" at 5376,3752 h100
  text "+5V" at 4233,3715 h100 r90
  text "GND" at 3382,3683 h100 r90
  text "GND" at 3895.04,3678 h100 r90
  text "GND" at 3157,3676 h100 r90
  text "nRST" at 2744,3655 h100 r90
  text "GND" at 2441,3646 h100 r90
  text "SYS ON" at 2846,3563 h100 r90
  text "DCDC 1" at 4440,3560 h100 r90
  text "I2C SCL" at 2539,3550 h100 r90
  text "I2C SDA" at 2643,3543 h100 r90
  text "nRST OUT" at 3694,3532 h80 r90
  text "GOPIO 2" at 3493,3529 h100 r90
  text "GOPIO 1" at 3593,3528 h100 r90
  text "PWR ON" at 2953,3524 h100 r90
  text "BAT FLT" at 3791,3503 h100 r90
  text "LDO4 Vin" at 4326,3492 h100 r90
  text "EXT_WAKE" at 3052,3488 h80 r90
  text "DC/DC # 3" at 5564,3472 h100
  text "Design by:" at 3103,3362 h120
  text "GND" at 5380,3358 h100
  text "www.novtech.com" at 3700,3121 h120
  text "(888) 701-7466" at 3846,3037 h90
Board Outline:
  the board outline again, w1
Board Info:
  drawing of 476 lines, arcs and shapes, not listed
  text "12" at 300,12950 h90
  text "11" at 300,11950 h90
  text "10" at 300,10950 h90
  text "9.0" at 300,9950 h90
  text "8.0" at 300,8950 h90
  text "7.0" at 300,7950 h90
  text "6.0" at 300,6950 h90
  text "5.0" at 300,5950 h90
  text "4.0" at 300,4950 h90
  text "3.0" at 300,3950 h90
  text "2.0" at 300,2950 h90
  text "NovTech, Inc." at 1500,2200 h70
  text "www.novtech.com" at 3500,2200 h50
  text "TITLE:" at 2287.5,1987.5 h45
  text "ENGINEER:" at 1400,1975 h45
  text "1.0" at 300,1950 h90
  text "Yossi Har-Nov" at 1500,1900 h50
  text "PHONE:" at 1400,1787.5 h45
  text "ENGINEER:" at 1400,1595 h45
  text "ENGINEER:" at 1400,1595 h45
  text "PART NO.:" at 2300,1512.5 h45
  text "REV:" at 4037.5,1512.5 h45
  text "DATE:" at 4500,1512.5 h45
  text "(954) 471-7281" at 1400,1500 h50
  text "(954) 471-7281" at 1400,1500 h50
  text ".PRINT_DATE" at 4725,1437.5 h90
  text "PHONE:" at 1400,1412.5 h45
  text "PHONE:" at 1400,1412.5 h45
  text "FILE NAME:" at 1400,1235 h45
  text "FILE NAME:" at 1400,1235 h45
  text "LAYER:" at 3240,1235 h45
  text "GERBER:" at 5060,1235 h45
  text ".Layer_Name" at 5050,1150 h45
  text "0" at 387.5,950 h90
  text "0" at 387.5,950 h90
  text "Y" at 650,862.5 h90 r270
  text "Y" at 650,862.5 h90 r270
  text "1.0" at 1950,750 h90 r270
  text "1.0" at 1950,750 h90 r270
  text "2.0" at 2950,750 h90 r270
  text "3.0" at 3950,750 h90 r270
  text "4.0" at 4950,750 h90 r270
  text "5.0" at 5950,750 h90 r270
  text "6.0" at 6950,750 h90 r270
  text "7.0" at 7950,750 h90 r270
  text "8.0" at 8950,750 h90 r270
  text "9.0" at 9950,750 h90 r270
  text "10.0" at 10950,750 h90 r270
  text "X" at 812.5,650 h90
  text "X" at 812.5,650 h90
  text "0" at 950,450 h90 r270
  text "0" at 950,450 h90 r270
Assembly Designators Top:
  text "LP3971 EVB - TOP" at 3439,6473 h200
Drill Drawing:
  lines w5: 9576,4521.25 12331,4521.25 ; 9576,4616.45 12331,4616.45 ; 9516,3550 ccw(c9547,3550) 9547,3519 12360,3519 ccw(c12360,3550) 12391,3550 12391,4821 ccw(c12360,4821) 12360,4852 9547,4852 ccw(c9547,4821) 9516,4821 9516,3550
  text "1.   Controlling dimensions are in inches" at 9551,11895 h50
  text "2.   Positional; Tolerances: +/-0.005" at 9551,11795 h50
  text "Plated-thru drilled: +/-0.003" at 9776,11595 h50
  text "Plated-thru routed: +/-0.005" at 9776,11495 h50
  text "Non-Plated drilled: +/-0.002" at 9776,11395 h50
  text "Non-Plated routed: +/-0.005" at 9776,11295 h50
  text "4.   RoHS Compliance:" at 9551,11195 h50
  text "(X) Yes - Use lead Free process, high TG(170 + dgree C) material" at 9776,11095 h50
  text "( ) No - Fabricate for leaded assembly" at 9776,11020 h50
  text "5.   Material Specifications:" at 9551,10945 h50
  text "(X) FR4 or better" at 9776,10845 h50
  text "( ) CEM1" at 9776,10770 h50
  text "6.   Printed Circuit Board Thickness:" at 9551,10670 h50
  text "( ) 0.020 +/-0.003" at 9776,10570 h50
  text "( ) 0.047 +/-0.003" at 9776,10420 h50
  text "(X) 0.062+/-0.005" at 9776,10345 h50
  text "( ) 0.093+/-0.007" at 9776,10270 h50
  text "( ) 0.125+/-0.007" at 9776,10195 h50
  text "( ) OTHER - See Figure A" at 9776,10120 h50
  text "7.   Copper clad Outer layer thickness BP (before plating) per square foot:" at 9551,10020 h50
  text "( ) 0.375 oz. Copper BP" at 9776,9920 h50
  text "(X) 0.500 oz. Copper BP" at 9776,9845 h50
  text "( ) 1.000 oz. Copper BP" at 9776,9770 h50
  text "( ) 2.000 oz. Copper BP" at 9776,9695 h50
  text "( ) 3.000 oz. Copper BP" at 9776,9620 h50
  text "( ) OTHER - See Figure A" at 9776,9545 h50
  text "8.   Copper clad Inner layer thickness per square foot:" at 9551,9470 h50
  text "(X) 0.500 oz. Copper BP" at 9776,9395 h50
  text "( ) 1.000 oz. Copper BP" at 9776,9320 h50
  text "( ) OTHER - See Figure A" at 9776,9245 h50
  text "9.   Minimum Plating Thickness for Plated Holes: 0.001" at 9551,9145 h50
  text "10.  Layers are to be arranged as shown in Figure A" at 9551,9045 h50
  text "11.  Soldermask Process:" at 9551,8945 h50
  text "(X) SMOBC (soldermask over bare copper)" at 9776,8870 h50
  text "( ) SMOTL (soldermask over tin/lead)" at 9776,8795 h50
  text "( ) Bare copper, no soldermask" at 9776,8720 h50
  text "12.  Soldermask Specifications:" at 9551,8620 h50
  text "(X) LPI (liguid photo-imagable) soldermask on both sides of board" at 9776,8545 h50
  text "( ) Dry film soldermask on both sides of board" at 9776,8470 h50
  text "( ) Wet soldermask thermal cure or equivalent" at 9776,8395 h50
  text "13.  Soldermask Color:" at 9551,8295 h50
  text "(X) Green" at 9776,8220 h50
  text "( ) Red" at 9776,8145 h50
  text "( ) Blue" at 9776,8070 h50
  text "( ) Black" at 9776,7995 h50
  text "( ) White" at 9776,7920 h50
  text "14. Do not modify solder mask layers except to eliminate darns that are to small. Solder mask on vias is okay" at 9551,7845 h50
  text "15. Board Surface Finish:" at 9551,7745 h50
  text "( ) HASL (hot air solder leveled)" at 9776,7670 h50
  text "(X) ENIG-IPC 4552 electroless nickel (120-240 uln) + immersion gold (2-4 uln)" at 9776,7595 h50
  text "( ) ENEPIG-electroless nickel (120-240 uln) + electroless paladium (5-15 uln) + immersion gold flash (1-2 uln)" at 9776,7520 h50
  text "( ) IAg-IPC 4553 immersion silver (8-12 uln on 60x60 mil pad)" at 9776,7445 h50
  text "( ) IT/ISn/White Tin-immersion tin plating (30-50 uln)" at 9776,7370 h50
  text "( ) DIG-direct immersion gold, electroless gold + immersion gold (1-2 uln)" at 9776,7295 h50
  text "( ) OSP-organic solder preservative" at 9776,7220 h50
  text "( ) Bare copper, no surface finish" at 9776,7145 h50
  text "16. Contact Surface Finish:" at 9551,7045 h50
  text "Begin with ENIG-IPC 4552 elecroless nickel (120-240 uln) + immersion gold (2-4 uln), covered by additional 50 uln of" at 9726,6970 h50
  text "electroless gold. Contacts are located on Top layer and look similar to Figure B, below" at 9726,6895 h50
  text "17. Silckscreen Locations:" at 9551,6795 h50
  text "(X) Top & Bottom" at 9776,6720 h50
  text "( ) Top only" at 9776,6645 h50
  text "( ) Bottom only" at 9776,6570 h50
  text "( ) No silkscreen" at 9776,6495 h50
  text "18. Silkscreen Ink Color:" at 9551,6420 h50
  text "(X) White" at 9776,6345 h50
  text "( ) Yellow" at 9776,6270 h50
  text "( ) Black" at 9776,6195 h50
  text "19.  UL Requirments:" at 9551,6120 h50
  text "(X) PCB to be manufactured by a UL recognized facility and to have a finish flame rating of UL 94V-0" at 9776,6045 h50
  text "( ) Manufacturer shall affix its UL recognized logo and the characters 94V-0 on the PCB in etched copper on top layer" at 9776,5970 h50
  text "at location indicated by XXXXXXXX on fabrication drawing" at 9951,5895 h50
  text "20.  Impedance Control:" at 9551,5820 h50
  text "Internal dimensions shwon in Figure A can be modified to meet the following impedance requirement. Dielectric" at 9801,5720 h50
  text "thickness and composition and trace widths may be modified to meet impedance and overall thickness requirements" at 9801,5645 h50
  text "Impedance control is required for the traces of 0.0149'' (0.3800mm) width. These traces must have a characteristic" at 9801,5570 h50
  text "Impedance of 50 ohms +/- 10%, measured at a frequency of 133.33MHz or greater. Note that impedance is set by trace" at 9801,5495 h50
  text "widht on layer 6, distance from surrounding ground plane on layer 6, and distance from ground plane on layer 5" at 9801,5420 h50
  text "Figure A" at 9526,5070 h50
  text "Layer Stack Up Detail for: LP3971_EVB_V10.PcbDoc" at 9576,4691.93 h56
  text "Layer" at 9576,4580.95 h22
  text "Gerber" at 10169,4580.95 h22
  text "Copper" at 10462.16,4580.95 h22
  text "Dielectric" at 10791.24,4580.95 h22
  text "Dielectric" at 11135.72,4580.95 h22
  text "Dielectric" at 11573.76,4580.95 h22
  text "Dielectric" at 11918.24,4580.95 h22
  text "Name" at 9576,4536.95 h22
  text "Document" at 10169,4536.95 h22
  text "Thickness" at 10462.16,4536.95 h22
  text "Height" at 10791.24,4536.95 h22
  text "Material" at 11135.72,4536.95 h22
  text "Constant" at 11573.76,4536.95 h22
  text "Type" at 11918.24,4536.95 h22
  text "Top Solder Mask" at 9576,4449.32 h31
  text "(.GTS)" at 10169,4449.32 h31
  text "0.4mil" at 10791.24,4449.32 h31
  text "Solder Resist" at 11135.72,4449.32 h31
  text "3.50" at 11573.76,4449.32 h31
  text "Top Layer" at 9576,4310.47 h31
  text "(.GTL)" at 10169,4310.47 h31
  text "1.4mil" at 10462.16,4310.47 h31
  text "5mil" at 10791.24,4241.04 h31
  text "FR-4" at 11135.72,4241.04 h31
  text "4.80" at 11573.76,4241.04 h31
  text "PrePreg" at 11918.24,4241.04 h31
  text "InternalPlane1" at 9576,4171.61 h31
  text "(.GP1)" at 10169,4171.61 h31
  text "1.4mil" at 10462.16,4171.61 h31
  text "46.4mil" at 10791.24,4102.19 h31
  text "FR-4" at 11135.72,4102.19 h31
  text "4.80" at 11573.76,4102.19 h31
  text "Core" at 11918.24,4102.19 h31
  text "InternalPlane2" at 9576,4032.76 h31
  text "(.GP2)" at 10169,4032.76 h31
  text "1.4mil" at 10462.16,4032.76 h31
  text "5mil" at 10791.24,3963.33 h31
  text "FR-4" at 11135.72,3963.33 h31
  text "4.80" at 11573.76,3963.33 h31
  text "PrePreg" at 11918.24,3963.33 h31
  text "Bottom Layer" at 9576,3893.91 h31
  text "(.GBL)" at 10169,3893.91 h31
  text "1.4mil" at 10462.16,3893.91 h31
  text "Bottom Solder Mask" at 9576,3755.05 h31
  text "(.GBS)" at 10169,3755.05 h31
  text "0.4mil" at 10791.24,3755.05 h31
  text "Solder Resist" at 11135.72,3755.05 h31
  text "3.50" at 11573.76,3755.05 h31
  text ".Legend" at 12776,3270 h50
